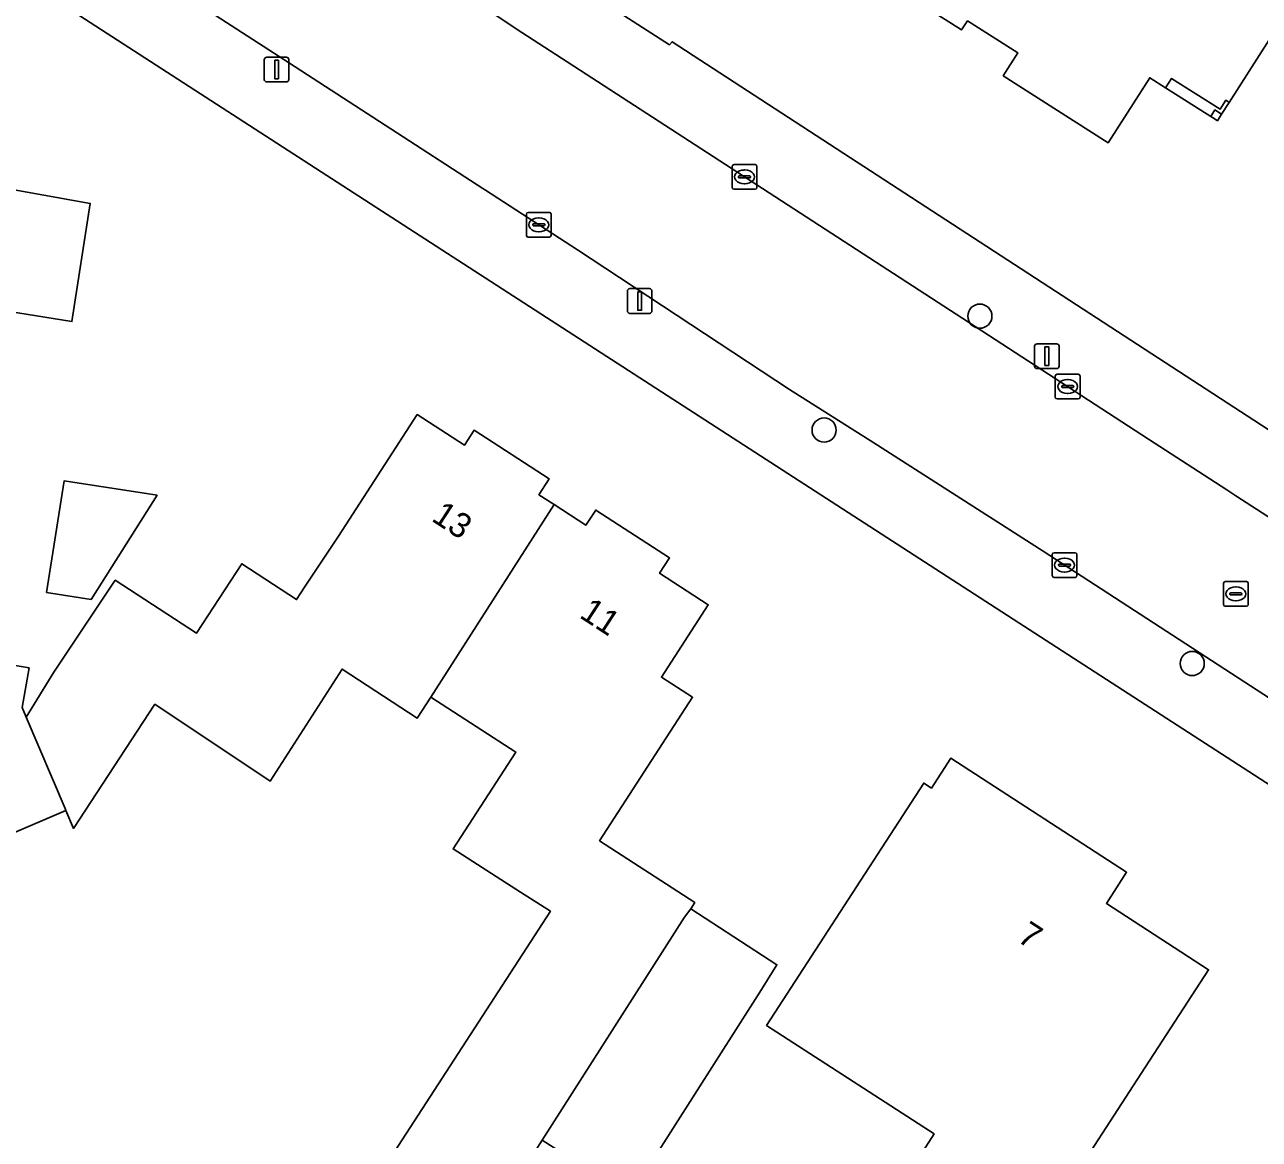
# Model space of a CAD drawing. Extents: x 161139 to 161601, y 381708 to 382245.
# Drawn here: x 161296.54 to 161346.45, y 381929.18 to 381974.24 of the extents above; entities that cross this region are included whole.
import ezdxf

# ---------------------------------------------------------------- set-up
doc = ezdxf.new("R2010")
doc.units = 0
for name, color, linetype in [('IMGEO_Boom', 7, 'Continuous'), ('IMGEO_Erf', 7, 'Continuous'), ('IMGEO_Kolk', 7, 'Continuous'), ('IMGEO_Lichtmast', 7, 'Continuous'), ('IMGEO_Pand', 7, 'Continuous'), ('IMGEO_Pand_nummerreeks', 7, 'Continuous'), ('IMGEO_Pand_overbouw', 7, 'Continuous'), ('IMGEO_Rijbaan_lokaal_open', 7, 'Continuous'), ('IMGEO_Rioolput', 7, 'Continuous'), ('IMGEO_Voetpad_open', 7, 'Continuous')]:
    doc.layers.add(name, color=color, linetype=linetype)

msp = doc.modelspace()

# ---------------------------------------------------------------- linework, layer by layer
at = {"layer": 'IMGEO_Boom'}
for centre in [(161335.154, 381962.458), (161328.858, 381957.854), (161343.738, 381948.417)]:
    msp.add_circle(centre, 0.489, dxfattribs=at)
at = {"layer": 'IMGEO_Erf'}
for points in [[(161301.893, 382073.339), (161290.838, 382055.877), (161287.538, 382048.363), (161285.187, 382041.077), (161283.628, 382034.817), (161278.294, 382002.287), (161281.877, 382000), (161299.823, 381988.353), (161310.674, 381981.109), (161322.611, 381973.432), (161322.712, 381973.551), (161378.924, 381936.994), (161385.641, 381932.206), (161392.817, 381926.552), (161429.313, 381896.994)], [(161370.462, 381928.258), (161276.309, 381989.126), (161276.14, 381989.025), (161267.873, 381937.797), (161267.435, 381933.784), (161267.467, 381929.855), (161267.871, 381925.589), (161268.634, 381921.624), (161269.796, 381917.444), (161271.533, 381912.948), (161272.783, 381910.378), (161277.045, 381903.774)], [(161295.664, 381948.413), (161296.72, 381948.236), (161296.441, 381946.64), (161296.607, 381946.251), (161297.721, 381948.068), (161300.204, 381951.783), (161303.481, 381949.642), (161305.314, 381952.447), (161307.532, 381950.998), (161307.878, 381951.537), (161309.224, 381953.565), (161312.409, 381958.477), (161314.316, 381957.241), (161314.709, 381957.847), (161317.744, 381955.877), (161317.332, 381955.241), (161317.942, 381954.845), (161319.229, 381954.011), (161319.625, 381954.622), (161322.611, 381952.686), (161322.208, 381952.066), (161324.177, 381950.789), (161322.283, 381947.869), (161323.542, 381947.053), (161319.778, 381941.251), (161323.627, 381938.754), (161323.465, 381938.504), (161326.953, 381936.241), (161326.262, 381935.133), (161321.004, 381926.887)], [(161311.476, 381928.656), (161317.797, 381938.4), (161316.587, 381939.175), (161313.857, 381940.924), (161316.394, 381944.835), (161312.965, 381947.06), (161312.408, 381946.208), (161309.369, 381948.193), (161306.469, 381943.662), (161301.803, 381946.771), (161298.521, 381941.748), (161298.211, 381942.48), (161296.04, 381941.544)]]:
    msp.add_lwpolyline(points, dxfattribs=at)
for points in [[(161345.229, 381971.099), (161345.094, 381971.185), (161344.863, 381970.822), (161342.904, 381972.07), (161342.662, 381971.691), (161342.021, 381972.099), (161340.338, 381969.467), (161336.1, 381972.176), (161336.689, 381973.098), (161334.659, 381974.396), (161334.413, 381974.038), (161329.982, 381976.855), (161332.06, 381980.096), (161331.431, 381980.495), (161336.33, 381988.176), (161341.044, 381985.169), (161339.024, 381982.002), (161345.419, 381977.923), (161346.226, 381979.188), (161349.184, 381977.301)], [(161291.811, 381958.087), (161279.219, 381960.153), (161281.395, 381973.911), (161294.018, 381971.914), (161293.408, 381968.055), (161299.194, 381967.02), (161298.451, 381962.239), (161292.636, 381963.173)], [(161344.756, 381970.357), (161344.621, 381970.443), (161344.486, 381970.529), (161344.658, 381970.798), (161344.928, 381970.626)], [(161297.43, 381951.283), (161298.141, 381955.806), (161301.894, 381955.216), (161299.225, 381951.001)], [(161326.534, 381933.789), (161330.165, 381939.387), (161332.886, 381943.581), (161333.193, 381943.382), (161333.975, 381944.588), (161341.086, 381939.976), (161340.269, 381938.717), (161344.399, 381936.038), (161341.679, 381931.844), (161336.953, 381924.571), (161332.168, 381927.644), (161333.306, 381929.397)]]:
    msp.add_lwpolyline(points, close=True, dxfattribs=at)
at = {"layer": 'IMGEO_Kolk'}
for p, q in [((161325.141, 381967.662), (161325.141, 381968.514)), ((161325.216, 381968.588), (161326.068, 381968.588)), ((161326.142, 381968.514), (161326.142, 381967.662)), ((161325.4, 381968.082), (161325.4, 381968.094)), ((161325.838, 381968.045), (161325.44, 381968.045)), ((161325.443, 381968.131), (161325.841, 381968.131)), ((161325.629, 381968.368), (161325.654, 381968.368)), ((161325.884, 381968.094), (161325.884, 381968.082)), ((161326.068, 381967.588), (161325.216, 381967.588)), ((161325.652, 381967.808), (161325.627, 381967.808)), ((161316.823, 381965.726), (161316.823, 381966.578)), ((161316.898, 381966.652), (161317.75, 381966.652)), ((161317.311, 381966.432), (161317.336, 381966.432)), ((161317.824, 381966.578), (161317.824, 381965.726)), ((161317.082, 381966.146), (161317.082, 381966.158)), ((161317.52, 381966.109), (161317.122, 381966.109)), ((161317.125, 381966.195), (161317.523, 381966.195)), ((161317.566, 381966.158), (161317.566, 381966.146)), ((161317.75, 381965.652), (161316.898, 381965.652)), ((161317.334, 381965.872), (161317.309, 381965.872)), ((161338.203, 381959.187), (161338.203, 381960.039)), ((161338.278, 381960.113), (161339.13, 381960.113)), ((161338.691, 381959.893), (161338.716, 381959.893)), ((161339.204, 381960.039), (161339.204, 381959.187)), ((161338.462, 381959.607), (161338.462, 381959.619)), ((161338.9, 381959.57), (161338.502, 381959.57)), ((161338.505, 381959.656), (161338.903, 381959.656)), ((161338.946, 381959.619), (161338.946, 381959.607)), ((161339.13, 381959.113), (161338.278, 381959.113)), ((161338.714, 381959.333), (161338.689, 381959.333)), ((161338.077, 381951.969), (161338.077, 381952.821)), ((161338.152, 381952.895), (161339.004, 381952.895)), ((161338.379, 381952.438), (161338.777, 381952.438)), ((161338.565, 381952.675), (161338.59, 381952.675)), ((161339.078, 381952.821), (161339.078, 381951.969)), ((161338.336, 381952.389), (161338.336, 381952.401)), ((161338.774, 381952.352), (161338.376, 381952.352)), ((161338.588, 381952.115), (161338.563, 381952.115)), ((161338.82, 381952.401), (161338.82, 381952.389)), ((161339.004, 381951.895), (161338.152, 381951.895))]:
    msp.add_line(p, q, dxfattribs=at)
for points in [[(161325.141, 381967.662), (161325.141, 381968.514)], [(161325.216, 381968.588), (161326.068, 381968.588)], [(161326.142, 381968.514), (161326.142, 381967.662)], [(161326.068, 381967.588), (161325.216, 381967.588)], [(161316.823, 381965.726), (161316.823, 381966.578)], [(161316.898, 381966.652), (161317.75, 381966.652)], [(161317.824, 381966.578), (161317.824, 381965.726)], [(161317.75, 381965.652), (161316.898, 381965.652)], [(161338.203, 381959.187), (161338.203, 381960.039)], [(161338.278, 381960.113), (161339.13, 381960.113)], [(161339.204, 381960.039), (161339.204, 381959.187)], [(161339.13, 381959.113), (161338.278, 381959.113)], [(161338.077, 381951.969), (161338.077, 381952.821)], [(161338.152, 381952.895), (161339.004, 381952.895)], [(161339.078, 381952.821), (161339.078, 381951.969)], [(161339.004, 381951.895), (161338.152, 381951.895)]]:
    msp.add_lwpolyline(points, dxfattribs=at)
for centre, radius, start, end in [((161325.218, 381968.512), 0.0765, 91.552, 178.448), ((161325.218, 381968.512), 0.0765, 91.552, 178.448), ((161326.066, 381968.512), 0.0765, 1.552, 88.448), ((161326.066, 381968.512), 0.0765, 1.552, 88.448), ((161325.44, 381968.091), 0.0403, 85.8775, 175.7526), ((161325.437, 381968.081), 0.0366, 178.938, 274.7102), ((161325.841, 381968.088), 0.043, 264.8664, 352.4533), ((161325.845, 381968.093), 0.0386, 1.7309, 96.639), ((161325.218, 381967.664), 0.0765, 181.552, 268.448), ((161325.218, 381967.664), 0.0765, 181.552, 268.448), ((161326.066, 381967.664), 0.0765, 271.552, 358.448), ((161326.066, 381967.664), 0.0765, 271.552, 358.448), ((161316.9, 381966.576), 0.0765, 91.552, 178.448), ((161316.9, 381966.576), 0.0765, 91.552, 178.448), ((161317.748, 381966.576), 0.0765, 1.552, 88.448), ((161317.748, 381966.576), 0.0765, 1.552, 88.448), ((161317.122, 381966.155), 0.0403, 85.8775, 175.7526), ((161317.119, 381966.145), 0.0366, 178.938, 274.7102), ((161317.523, 381966.152), 0.043, 264.8664, 352.4533), ((161317.527, 381966.157), 0.0386, 1.7309, 96.639), ((161316.9, 381965.728), 0.0765, 181.552, 268.448), ((161316.9, 381965.728), 0.0765, 181.552, 268.448), ((161317.748, 381965.728), 0.0765, 271.552, 358.448), ((161317.748, 381965.728), 0.0765, 271.552, 358.448), ((161338.28, 381960.037), 0.0765, 91.552, 178.448), ((161338.28, 381960.037), 0.0765, 91.552, 178.448), ((161339.128, 381960.037), 0.0765, 1.552, 88.448), ((161339.128, 381960.037), 0.0765, 1.552, 88.448), ((161338.502, 381959.616), 0.0403, 85.8775, 175.7526), ((161338.499, 381959.606), 0.0366, 178.938, 274.7102), ((161338.903, 381959.613), 0.043, 264.8664, 352.4533), ((161338.907, 381959.618), 0.0386, 1.7309, 96.639), ((161338.28, 381959.189), 0.0765, 181.552, 268.448), ((161338.28, 381959.189), 0.0765, 181.552, 268.448), ((161339.128, 381959.189), 0.0765, 271.552, 358.448), ((161339.128, 381959.189), 0.0765, 271.552, 358.448), ((161338.154, 381952.819), 0.0765, 91.552, 178.448), ((161338.154, 381952.819), 0.0765, 91.552, 178.448), ((161338.376, 381952.398), 0.0403, 85.8775, 175.7526), ((161338.781, 381952.4), 0.0386, 1.7309, 96.639), ((161339.002, 381952.819), 0.0765, 1.552, 88.448), ((161339.002, 381952.819), 0.0765, 1.552, 88.448), ((161338.154, 381951.971), 0.0765, 181.552, 268.448), ((161338.154, 381951.971), 0.0765, 181.552, 268.448), ((161338.373, 381952.388), 0.0366, 178.938, 274.7102), ((161338.777, 381952.395), 0.043, 264.8664, 352.4533), ((161339.002, 381951.971), 0.0765, 271.552, 358.448), ((161339.002, 381951.971), 0.0765, 271.552, 358.448)]:
    msp.add_arc(centre, radius, start, end, dxfattribs=at)
for centre, major_axis, ratio, start_param, end_param in [((161325.628, 381968.088), (-0.387, 0.002), 0.722429, 4.712389, 7.853982), ((161325.653, 381968.088), (-0.39, 0.002), 0.717154, 1.570796, 4.712389), ((161317.31, 381966.152), (-0.387, 0.002), 0.722429, 4.712389, 7.853982), ((161317.335, 381966.152), (-0.39, 0.002), 0.717154, 1.570796, 4.712389), ((161338.69, 381959.613), (-0.387, 0.002), 0.722429, 4.712389, 7.853982), ((161338.715, 381959.613), (-0.39, 0.002), 0.717154, 1.570796, 4.712389), ((161338.564, 381952.395), (-0.387, 0.002), 0.722429, 4.712389, 7.853982), ((161338.589, 381952.395), (-0.39, 0.002), 0.717154, 1.570796, 4.712389)]:
    msp.add_ellipse(centre, major_axis=major_axis, ratio=ratio, start_param=start_param, end_param=end_param, dxfattribs=at)
at = {"layer": 'IMGEO_Lichtmast'}
for p, q in [((161306.329, 381972.929), (161307.119, 381972.929)), ((161307.119, 381972.929), (161306.329, 381972.929)), ((161306.229, 381972.029), (161306.229, 381972.829)), ((161306.229, 381972.829), (161306.229, 381972.029)), ((161307.219, 381972.829), (161307.219, 381972.029)), ((161307.219, 381972.029), (161307.219, 381972.829)), ((161307.119, 381971.929), (161306.329, 381971.929)), ((161306.329, 381971.929), (161307.119, 381971.929)), ((161320.907, 381962.672), (161320.907, 381963.472)), ((161320.907, 381963.472), (161320.907, 381962.672)), ((161321.007, 381963.572), (161321.797, 381963.572)), ((161321.797, 381963.572), (161321.007, 381963.572)), ((161321.897, 381963.472), (161321.897, 381962.672)), ((161321.897, 381962.672), (161321.897, 381963.472)), ((161321.797, 381962.572), (161321.007, 381962.572)), ((161321.007, 381962.572), (161321.797, 381962.572)), ((161337.365, 381960.441), (161337.365, 381961.241)), ((161337.365, 381961.241), (161337.365, 381960.441)), ((161337.465, 381961.341), (161338.255, 381961.341)), ((161338.255, 381961.341), (161337.465, 381961.341)), ((161338.355, 381961.241), (161338.355, 381960.441)), ((161338.355, 381960.441), (161338.355, 381961.241)), ((161338.255, 381960.341), (161337.465, 381960.341)), ((161337.465, 381960.341), (161338.255, 381960.341))]:
    msp.add_line(p, q, dxfattribs=at)
for points in [[(161306.649, 381972.804), (161306.799, 381972.804), (161306.799, 381972.054), (161306.649, 381972.054), (161306.649, 381972.804)], [(161321.327, 381963.447), (161321.477, 381963.447), (161321.477, 381962.697), (161321.327, 381962.697), (161321.327, 381963.447)], [(161337.785, 381961.216), (161337.935, 381961.216), (161337.935, 381960.466), (161337.785, 381960.466), (161337.785, 381961.216)]]:
    msp.add_lwpolyline(points, dxfattribs=at)
for centre, start, end in [((161306.329, 381972.829), 90, 180), ((161306.329, 381972.829), 90, 180), ((161307.119, 381972.829), 0, 90), ((161307.119, 381972.829), 360, 90), ((161306.329, 381972.029), 180, 270), ((161306.329, 381972.029), 180, 270), ((161307.119, 381972.029), 270, 0), ((161307.119, 381972.029), 270, 0), ((161321.007, 381963.472), 90, 180), ((161321.007, 381963.472), 90, 180), ((161321.797, 381963.472), 0, 90), ((161321.797, 381963.472), 360, 90), ((161321.007, 381962.672), 180, 270), ((161321.007, 381962.672), 180, 270), ((161321.797, 381962.672), 270, 0), ((161321.797, 381962.672), 270, 0), ((161337.465, 381961.241), 90, 180), ((161337.465, 381961.241), 90, 180), ((161338.255, 381961.241), 0, 90), ((161338.255, 381961.241), 360, 90), ((161337.465, 381960.441), 180, 270), ((161337.465, 381960.441), 180, 270), ((161338.255, 381960.441), 270, 0), ((161338.255, 381960.441), 270, 0)]:
    msp.add_arc(centre, 0.1, start, end, dxfattribs=at)
at = {"layer": 'IMGEO_Pand'}
for points in [[(161349.184, 381977.301), (161346.226, 381979.188), (161345.419, 381977.923), (161339.024, 381982.002), (161341.044, 381985.169), (161336.33, 381988.176), (161331.431, 381980.495), (161332.06, 381980.096), (161329.982, 381976.855), (161334.413, 381974.038), (161334.659, 381974.396), (161336.689, 381973.098), (161336.1, 381972.176), (161340.338, 381969.467), (161342.021, 381972.099), (161342.662, 381971.691), (161342.904, 381972.07), (161344.863, 381970.822), (161345.094, 381971.185), (161345.229, 381971.099)], [(161294.018, 381971.914), (161281.395, 381973.911), (161279.219, 381960.153), (161291.811, 381958.087), (161292.636, 381963.173), (161298.451, 381962.239), (161299.194, 381967.02), (161293.408, 381968.055)], [(161344.928, 381970.626), (161344.658, 381970.798), (161344.486, 381970.529), (161344.621, 381970.443), (161344.756, 381970.357)], [(161317.942, 381954.845), (161317.332, 381955.241), (161317.744, 381955.877), (161314.709, 381957.847), (161314.316, 381957.241), (161312.409, 381958.477), (161309.224, 381953.565), (161307.878, 381951.537), (161307.532, 381950.998), (161305.314, 381952.447), (161303.481, 381949.642), (161300.204, 381951.783), (161297.721, 381948.068), (161296.607, 381946.251), (161298.176, 381942.561), (161298.211, 381942.48), (161298.521, 381941.748), (161301.803, 381946.771), (161306.469, 381943.662), (161309.369, 381948.193), (161312.408, 381946.208), (161312.965, 381947.06)], [(161297.43, 381951.283), (161299.225, 381951.001), (161301.894, 381955.216), (161298.141, 381955.806)], [(161319.778, 381941.251), (161323.542, 381947.053), (161322.283, 381947.869), (161324.177, 381950.789), (161322.208, 381952.066), (161322.611, 381952.686), (161319.625, 381954.622), (161319.229, 381954.011), (161317.942, 381954.845), (161312.965, 381947.06), (161316.394, 381944.835), (161313.857, 381940.924), (161316.587, 381939.175), (161317.797, 381938.4), (161311.476, 381928.656), (161315.487, 381926.054), (161317.459, 381929.147), (161323.208, 381938.163), (161323.465, 381938.504), (161323.627, 381938.754)], [(161341.679, 381931.844), (161344.399, 381936.038), (161340.269, 381938.717), (161341.086, 381939.976), (161333.975, 381944.588), (161333.193, 381943.382), (161332.886, 381943.581), (161330.165, 381939.387), (161326.534, 381933.789), (161333.306, 381929.397), (161332.168, 381927.644), (161336.953, 381924.571)], [(161326.262, 381935.133), (161326.953, 381936.241), (161323.465, 381938.504), (161323.208, 381938.163), (161317.459, 381929.147), (161321.004, 381926.887)]]:
    msp.add_lwpolyline(points, close=True, dxfattribs=at)
msp.add_lwpolyline([(161296.04, 381941.544), (161298.211, 381942.48), (161298.176, 381942.561), (161296.607, 381946.251), (161296.441, 381946.64), (161296.72, 381948.236), (161295.664, 381948.413)], dxfattribs=at)
at = {"layer": 'IMGEO_Pand_overbouw'}
msp.add_lwpolyline([(161342.662, 381971.691), (161344.486, 381970.529), (161344.621, 381970.443), (161344.756, 381970.357), (161344.928, 381970.626), (161345.229, 381971.099), (161345.094, 381971.185), (161344.863, 381970.822), (161342.904, 381972.07)], close=True, dxfattribs=at)
at = {"layer": 'IMGEO_Rijbaan_lokaal_open'}
for points in [[(161354.44, 381949.434), (161345.5, 381955.194), (161345.132, 381955.433), (161341.968, 381957.49), (161334.965, 381962.043), (161325.373, 381968.263), (161318.237, 381972.89), (161316.637, 381973.927), (161310.106, 381978.294), (161303.837, 381982.304), (161300.012, 381984.75), (161296.327, 381987.12), (161278.737, 381998.431)], [(161278.323, 381991.478), (161299.753, 381977.533), (161307.482, 381972.536), (161311.114, 381970.18), (161315.062, 381967.62), (161315.173, 381967.548), (161318.89, 381965.138), (161327.462, 381959.489), (161330.866, 381957.332), (161337.714, 381952.958), (161346.638, 381947.161), (161350.625, 381944.584), (161357.825, 381939.931), (161366.222, 381934.52), (161372.037, 381930.857), (161375.083, 381928.811)]]:
    msp.add_lwpolyline(points, dxfattribs=at)
at = {"layer": 'IMGEO_Rioolput'}
for p, q in [((161345.001, 381950.806), (161345.001, 381951.658)), ((161345.076, 381951.732), (161345.928, 381951.732)), ((161345.489, 381951.512), (161345.514, 381951.512)), ((161346.002, 381951.658), (161346.002, 381950.806)), ((161345.26, 381951.226), (161345.26, 381951.238)), ((161345.698, 381951.189), (161345.3, 381951.189)), ((161345.303, 381951.275), (161345.701, 381951.275)), ((161345.512, 381950.952), (161345.487, 381950.952)), ((161345.744, 381951.238), (161345.744, 381951.226)), ((161345.928, 381950.732), (161345.076, 381950.732))]:
    msp.add_line(p, q, dxfattribs=at)
for points in [[(161345.001, 381950.806), (161345.001, 381951.658)], [(161345.076, 381951.732), (161345.928, 381951.732)], [(161346.002, 381951.658), (161346.002, 381950.806)], [(161345.928, 381950.732), (161345.076, 381950.732)]]:
    msp.add_lwpolyline(points, dxfattribs=at)
for centre, radius, start, end in [((161345.078, 381951.656), 0.0765, 91.552, 178.448), ((161345.078, 381951.656), 0.0765, 91.552, 178.448), ((161345.926, 381951.656), 0.0765, 1.552, 88.448), ((161345.926, 381951.656), 0.0765, 1.552, 88.448), ((161345.3, 381951.235), 0.0403, 85.8775, 175.7526), ((161345.297, 381951.225), 0.0366, 178.938, 274.7102), ((161345.701, 381951.232), 0.043, 264.8664, 352.4533), ((161345.705, 381951.237), 0.0386, 1.7309, 96.639), ((161345.078, 381950.808), 0.0765, 181.552, 268.448), ((161345.078, 381950.808), 0.0765, 181.552, 268.448), ((161345.926, 381950.808), 0.0765, 271.552, 358.448), ((161345.926, 381950.808), 0.0765, 271.552, 358.448)]:
    msp.add_arc(centre, radius, start, end, dxfattribs=at)
for centre, major_axis, ratio, start_param, end_param in [((161345.488, 381951.232), (-0.387, 0.002), 0.722429, 4.712389, 7.853982), ((161345.513, 381951.232), (-0.39, 0.002), 0.717154, 1.570796, 4.712389)]:
    msp.add_ellipse(centre, major_axis=major_axis, ratio=ratio, start_param=start_param, end_param=end_param, dxfattribs=at)
at = {"layer": 'IMGEO_Voetpad_open'}
for points in [[(161392.817, 381926.552), (161385.641, 381932.206), (161378.924, 381936.994), (161322.712, 381973.551), (161322.611, 381973.432), (161310.674, 381981.109), (161299.823, 381988.353), (161281.877, 382000)], [(161327.462, 381959.489), (161318.89, 381965.138), (161315.173, 381967.548), (161315.062, 381967.62), (161311.114, 381970.18), (161307.482, 381972.536), (161299.753, 381977.533), (161278.323, 381991.478), (161276.309, 381989.126), (161370.462, 381928.258), (161376.195, 381924.445)], [(161296.327, 381987.12), (161300.012, 381984.75), (161303.837, 381982.304), (161310.106, 381978.294), (161316.637, 381973.927), (161318.237, 381972.89), (161325.373, 381968.263), (161334.965, 381962.043), (161341.968, 381957.49), (161345.132, 381955.433), (161345.5, 381955.194), (161354.44, 381949.434), (161361.946, 381944.451), (161364.318, 381942.933), (161367.432, 381940.939), (161370.251, 381939.135), (161376.383, 381935.18), (161381.315, 381931.756), (161381.728, 381931.469), (161384.971, 381929.006)], [(161375.58, 381928.429), (161375.083, 381928.811), (161372.037, 381930.857), (161366.222, 381934.52), (161357.825, 381939.931), (161350.625, 381944.584), (161346.638, 381947.161), (161337.714, 381952.958), (161330.866, 381957.332), (161327.462, 381959.489)]]:
    msp.add_lwpolyline(points, dxfattribs=at)

# ---------------------------------------------------------------- texts
at = {"layer": 'IMGEO_Pand_nummerreeks'}
for s, rotation, p in [('13', 326.8429, (161312.942, 381954.211)), ('11', 326.8429, (161318.921, 381950.305)), ('7', 326.7683, (161336.615, 381937.217))]:
    msp.add_text(s, height=1, rotation=rotation, dxfattribs=at).set_placement(p)

doc.saveas('drawing.dxf')
